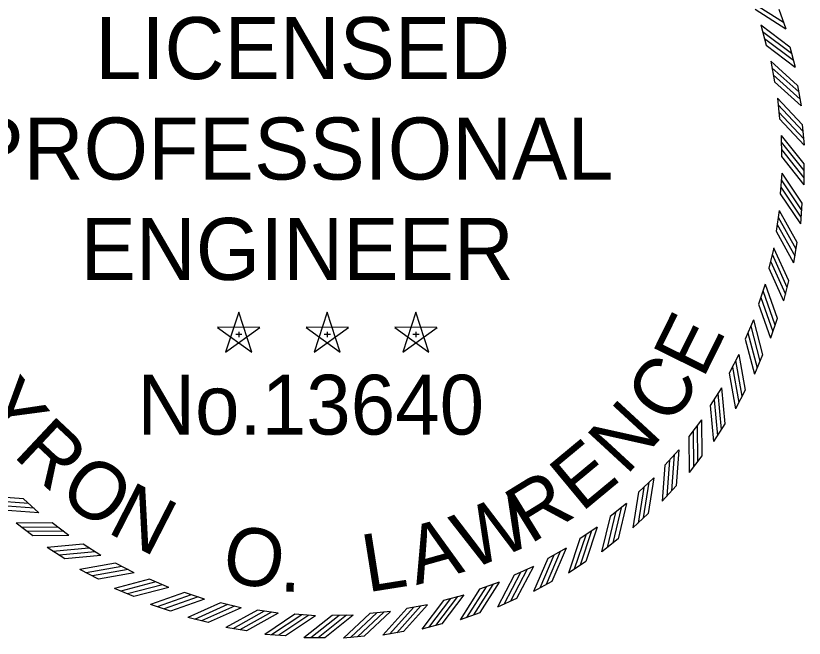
# Model space of a CAD drawing. Extents: x 166 to 3995, y -61 to 2074.
# Drawn here: x 2721.4 to 2926.8, y 412.6 to 574.8 of the extents above; entities that cross this region are included whole.
import ezdxf

# ---------------------------------------------------------------- set-up
doc = ezdxf.new("R2010")
doc.units = 0
doc.layers.add('STAMP_Byron', color=7, linetype='Continuous')

msp = doc.modelspace()

# ---------------------------------------------------------------- linework, layer by layer
at = {"layer": 'STAMP_Byron'}
for p, q in [((2920.12, 576.55), (2921.94, 571.42)), ((2920.12, 576.55), (2921.94, 571.42)), ((2915.51, 572.41), (2916.9, 567.14)), ((2915.51, 572.41), (2916.9, 567.14)), ((2923, 566.71), (2924.38, 561.44)), ((2923, 566.71), (2924.38, 561.44)), ((2918.06, 562.96), (2919.01, 557.59)), ((2918.06, 562.96), (2919.01, 557.59)), ((2925.05, 556.66), (2926, 551.3)), ((2925.05, 556.66), (2926, 551.3)), ((2919.82, 553.34), (2920.32, 547.91)), ((2919.82, 553.34), (2920.32, 547.91)), ((2926.27, 546.47), (2926.77, 541.06)), ((2926.27, 546.47), (2926.77, 541.06)), ((2920.78, 543.6), (2920.83, 538.14)), ((2920.78, 543.6), (2920.83, 538.14)), ((2926.64, 536.22), (2926.69, 530.78)), ((2926.64, 536.22), (2926.69, 530.78)), ((2920.93, 533.81), (2920.53, 528.37)), ((2920.93, 533.81), (2920.53, 528.37)), ((2926.16, 525.98), (2925.76, 520.55)), ((2926.16, 525.98), (2925.76, 520.55)), ((2920.28, 524.04), (2919.43, 518.66)), ((2920.28, 524.04), (2919.43, 518.66)), ((2924.84, 515.81), (2924, 510.43)), ((2924.84, 515.81), (2924, 510.43)), ((2918.82, 514.37), (2917.53, 509.07)), ((2918.82, 514.37), (2917.53, 509.07)), ((2922.69, 505.78), (2921.4, 500.5)), ((2922.69, 505.78), (2921.4, 500.5)), ((2916.56, 504.84), (2914.84, 499.67)), ((2916.56, 504.84), (2914.84, 499.67)), ((2779.46, 497.61), (2776.06, 487.16)), ((2779.46, 497.61), (2776.06, 487.16)), ((2782.86, 487.17), (2779.47, 497.62)), ((2782.86, 487.17), (2779.47, 497.62)), ((2802.54, 497.61), (2799.14, 487.16)), ((2802.54, 497.61), (2799.14, 487.16)), ((2805.93, 487.17), (2802.55, 497.62)), ((2805.93, 487.17), (2802.55, 497.62)), ((2825.62, 497.61), (2822.22, 487.16)), ((2825.62, 497.61), (2822.22, 487.16)), ((2829.01, 487.17), (2825.63, 497.62)), ((2829.01, 487.17), (2825.63, 497.62)), ((2913.53, 495.54), (2911.39, 490.52)), ((2913.53, 495.54), (2911.39, 490.52)), ((2919.71, 495.97), (2917.99, 490.81)), ((2919.71, 495.97), (2917.99, 490.81)), ((2784.95, 493.62), (2773.97, 493.63)), ((2784.95, 493.62), (2773.97, 493.63)), ((2773.98, 493.62), (2782.86, 487.15)), ((2773.98, 493.62), (2782.86, 487.15)), ((2776.07, 487.17), (2784.96, 493.62)), ((2776.07, 487.17), (2784.96, 493.62)), ((2808.03, 493.62), (2797.05, 493.63)), ((2808.03, 493.62), (2797.05, 493.63)), ((2797.05, 493.62), (2805.93, 487.15)), ((2797.05, 493.62), (2805.93, 487.15)), ((2799.15, 487.17), (2808.04, 493.62)), ((2799.15, 487.17), (2808.04, 493.62)), ((2831.11, 493.62), (2820.12, 493.63)), ((2831.11, 493.62), (2820.12, 493.63)), ((2820.13, 493.62), (2829.01, 487.15)), ((2820.13, 493.62), (2829.01, 487.15)), ((2822.23, 487.17), (2831.12, 493.62)), ((2822.23, 487.17), (2831.12, 493.62)), ((2778.68, 491.86), (2780.31, 491.86)), ((2778.68, 491.86), (2780.31, 491.86)), ((2779.47, 492.45), (2779.47, 491.07)), ((2779.47, 492.45), (2779.47, 491.07)), ((2801.76, 491.86), (2803.39, 491.86)), ((2801.76, 491.86), (2803.39, 491.86)), ((2802.55, 492.45), (2802.55, 491.07)), ((2802.55, 492.45), (2802.55, 491.07)), ((2824.84, 491.86), (2826.47, 491.86)), ((2824.84, 491.86), (2826.47, 491.86)), ((2825.63, 492.45), (2825.63, 491.07)), ((2825.63, 492.45), (2825.63, 491.07)), ((2909.74, 486.51), (2907.19, 481.69)), ((2909.74, 486.51), (2907.19, 481.69)), ((2915.93, 486.43), (2913.79, 481.43)), ((2915.93, 486.43), (2913.79, 481.43)), ((2905.22, 477.83), (2902.27, 473.24)), ((2905.22, 477.83), (2902.27, 473.24)), ((2911.38, 477.24), (2908.84, 472.43)), ((2911.38, 477.24), (2908.84, 472.43)), ((2899.99, 469.56), (2896.68, 465.22)), ((2899.99, 469.56), (2896.68, 465.22)), ((2906.09, 468.46), (2903.15, 463.88)), ((2906.09, 468.46), (2903.15, 463.88)), ((2894.1, 461.74), (2890.44, 457.69)), ((2894.1, 461.74), (2890.44, 457.69)), ((2900.09, 460.14), (2896.78, 455.82)), ((2900.09, 460.14), (2896.78, 455.82)), ((2887.58, 454.44), (2883.61, 450.71)), ((2887.58, 454.44), (2883.61, 450.71)), ((2893.42, 452.35), (2889.77, 448.31)), ((2893.42, 452.35), (2889.77, 448.31)), ((2727.43, 445.31), (2723.39, 448.97)), ((2727.43, 445.31), (2723.39, 448.97)), ((2880.49, 447.7), (2876.22, 444.31)), ((2880.49, 447.7), (2876.22, 444.31)), ((2886.13, 445.13), (2882.16, 441.41)), ((2886.13, 445.13), (2882.16, 441.41)), ((2725.84, 439.32), (2721.51, 442.63)), ((2725.84, 439.32), (2721.51, 442.63)), ((2735.25, 439.42), (2730.92, 442.73)), ((2735.25, 439.42), (2730.92, 442.73)), ((2872.86, 441.56), (2868.32, 438.54)), ((2872.86, 441.56), (2868.32, 438.54)), ((2878.27, 438.55), (2874.01, 435.17)), ((2878.27, 438.55), (2874.01, 435.17)), ((2734.15, 433.32), (2729.57, 436.26)), ((2734.15, 433.32), (2729.57, 436.26)), ((2743.53, 434.19), (2738.94, 437.13)), ((2743.53, 434.19), (2738.94, 437.13)), ((2864.75, 436.08), (2859.98, 433.44)), ((2864.75, 436.08), (2859.98, 433.44)), ((2752.21, 429.67), (2747.39, 432.22)), ((2752.21, 429.67), (2747.39, 432.22)), ((2856.22, 431.29), (2851.24, 429.06)), ((2856.22, 431.29), (2851.24, 429.06)), ((2869.89, 432.63), (2865.36, 429.61)), ((2869.89, 432.63), (2865.36, 429.61)), ((2742.94, 428.03), (2738.13, 430.57)), ((2742.94, 428.03), (2738.13, 430.57)), ((2761.23, 425.88), (2756.22, 428.02)), ((2761.23, 425.88), (2756.22, 428.02)), ((2847.31, 427.22), (2842.17, 425.4)), ((2847.31, 427.22), (2842.17, 425.4)), ((2861.05, 427.42), (2856.29, 424.79)), ((2861.05, 427.42), (2856.29, 424.79)), ((2752.13, 423.48), (2747.12, 425.62)), ((2752.13, 423.48), (2747.12, 425.62)), ((2770.54, 422.85), (2765.36, 424.57)), ((2770.54, 422.85), (2765.36, 424.57)), ((2838.11, 423.9), (2832.83, 422.51)), ((2838.11, 423.9), (2832.83, 422.51)), ((2761.66, 419.7), (2756.5, 421.42)), ((2761.66, 419.7), (2756.5, 421.42)), ((2780.06, 420.59), (2774.76, 421.88)), ((2780.06, 420.59), (2774.76, 421.88)), ((2828.66, 421.35), (2823.29, 420.4)), ((2828.66, 421.35), (2823.29, 420.4)), ((2851.82, 422.97), (2846.86, 420.74)), ((2851.82, 422.97), (2846.86, 420.74)), ((2789.74, 419.13), (2784.35, 419.98)), ((2789.74, 419.13), (2784.35, 419.98)), ((2819.03, 419.59), (2813.6, 419.09)), ((2819.03, 419.59), (2813.6, 419.09)), ((2842.24, 419.29), (2837.12, 417.47)), ((2842.24, 419.29), (2837.12, 417.47)), ((2771.48, 416.72), (2766.19, 418.01)), ((2771.48, 416.72), (2766.19, 418.01)), ((2799.5, 418.48), (2794.07, 418.88)), ((2799.5, 418.48), (2794.07, 418.88)), ((2809.29, 418.63), (2803.84, 418.58)), ((2809.29, 418.63), (2803.84, 418.58)), ((2781.5, 414.57), (2776.13, 415.41)), ((2781.5, 414.57), (2776.13, 415.41)), ((2832.4, 416.41), (2827.14, 415.03)), ((2832.4, 416.41), (2827.14, 415.03)), ((2791.67, 413.25), (2786.25, 413.65)), ((2791.67, 413.25), (2786.25, 413.65)), ((2812.17, 413.14), (2806.75, 412.64)), ((2812.17, 413.14), (2806.75, 412.64)), ((2822.35, 414.36), (2816.99, 413.41)), ((2822.35, 414.36), (2816.99, 413.41)), ((2801.92, 412.77), (2796.48, 412.72)), ((2801.92, 412.77), (2796.48, 412.72))]:
    msp.add_line(p, q, dxfattribs=at)
for points in [[(2913.42, 578.2), (2921.35, 573.13)], [(2913.42, 578.2), (2921.35, 573.13)], [(2914.01, 576.49), (2921.94, 571.42)], [(2914.01, 576.49), (2921.94, 571.42)], [(2915.5, 572.42), (2922.99, 566.71)], [(2915.5, 572.42), (2922.99, 566.71)], [(2915.93, 570.72), (2923.42, 565.01)], [(2915.93, 570.72), (2923.42, 565.01)], [(2916.45, 568.9), (2923.94, 563.2)], [(2916.45, 568.9), (2923.94, 563.2)], [(2916.9, 567.15), (2924.39, 561.44)], [(2916.9, 567.15), (2924.39, 561.44)], [(2918.05, 562.97), (2925.05, 556.66)], [(2918.05, 562.97), (2925.05, 556.66)], [(2918.34, 561.24), (2925.33, 554.94)], [(2918.34, 561.24), (2925.33, 554.94)], [(2918.71, 559.39), (2925.7, 553.08)], [(2918.71, 559.39), (2925.7, 553.08)], [(2919.01, 557.6), (2926, 551.29)], [(2919.01, 557.6), (2926, 551.29)], [(2919.82, 553.34), (2926.26, 546.48)], [(2919.82, 553.34), (2926.26, 546.48)], [(2919.96, 551.6), (2926.41, 544.74)], [(2919.96, 551.6), (2926.41, 544.74)], [(2920.18, 549.72), (2926.62, 542.86)], [(2920.18, 549.72), (2926.62, 542.86)], [(2920.33, 547.91), (2926.77, 541.05)], [(2920.33, 547.91), (2926.77, 541.05)], [(2920.78, 543.6), (2926.63, 536.23)], [(2920.78, 543.6), (2926.63, 536.23)], [(2920.78, 541.85), (2926.63, 534.48)], [(2920.78, 541.85), (2926.63, 534.48)], [(2920.84, 539.96), (2926.69, 532.59)], [(2920.84, 539.96), (2926.69, 532.59)], [(2920.84, 538.15), (2926.69, 530.78)], [(2920.84, 538.15), (2926.69, 530.78)], [(2920.79, 532.07), (2926.01, 524.24)], [(2920.79, 532.07), (2926.01, 524.24)], [(2920.93, 533.82), (2926.16, 525.99)], [(2920.93, 533.82), (2926.16, 525.99)], [(2920.69, 530.18), (2925.92, 522.35)], [(2920.69, 530.18), (2925.92, 522.35)], [(2920.54, 528.38), (2925.77, 520.55)], [(2920.54, 528.38), (2925.77, 520.55)], [(2920.27, 524.05), (2924.84, 515.82)], [(2920.27, 524.05), (2924.84, 515.82)], [(2919.99, 522.32), (2924.55, 514.09)], [(2919.99, 522.32), (2924.55, 514.09)], [(2919.73, 520.45), (2924.3, 512.22)], [(2919.73, 520.45), (2924.3, 512.22)], [(2919.44, 518.66), (2924, 510.43)], [(2919.44, 518.66), (2924, 510.43)], [(2918.81, 514.37), (2922.68, 505.79)], [(2918.81, 514.37), (2922.68, 505.79)], [(2918.38, 512.68), (2922.25, 504.09)], [(2918.38, 512.68), (2922.25, 504.09)], [(2917.98, 510.83), (2921.85, 502.25)], [(2917.98, 510.83), (2921.85, 502.25)], [(2917.53, 509.07), (2921.4, 500.49)], [(2917.53, 509.07), (2921.4, 500.49)], [(2915.99, 503.19), (2919.14, 494.32)], [(2915.99, 503.19), (2919.14, 494.32)], [(2916.56, 504.85), (2919.71, 495.98)], [(2916.56, 504.85), (2919.71, 495.98)], [(2915.43, 501.39), (2918.58, 492.51)], [(2915.43, 501.39), (2918.58, 492.51)], [(2914.85, 499.67), (2917.99, 490.8)], [(2914.85, 499.67), (2917.99, 490.8)], [(2913.53, 495.54), (2915.93, 486.44)], [(2913.53, 495.54), (2915.93, 486.44)], [(2912.82, 493.94), (2915.23, 484.84)], [(2912.82, 493.94), (2915.23, 484.84)], [(2912.12, 492.19), (2914.52, 483.08)], [(2912.12, 492.19), (2914.52, 483.08)], [(2911.39, 490.53), (2913.8, 481.42)], [(2911.39, 490.53), (2913.8, 481.42)], [(2908.9, 484.98), (2910.55, 475.71)], [(2908.9, 484.98), (2910.55, 475.71)], [(2909.74, 486.52), (2911.38, 477.25)], [(2909.74, 486.52), (2911.38, 477.25)], [(2908.06, 483.29), (2909.7, 474.02)], [(2908.06, 483.29), (2909.7, 474.02)], [(2907.19, 481.7), (2908.84, 472.43)], [(2907.19, 481.7), (2908.84, 472.43)], [(2905.21, 477.84), (2906.09, 468.47)], [(2905.21, 477.84), (2906.09, 468.47)], [(2903.27, 474.76), (2904.15, 465.39)], [(2903.27, 474.76), (2904.15, 465.39)], [(2904.26, 476.37), (2905.13, 467)], [(2904.26, 476.37), (2905.13, 467)], [(2902.28, 473.24), (2903.15, 463.87)], [(2902.28, 473.24), (2903.15, 463.87)], [(2899.99, 469.56), (2900.09, 460.15)], [(2899.99, 469.56), (2900.09, 460.15)], [(2897.8, 466.66), (2897.9, 457.24)], [(2897.8, 466.66), (2897.9, 457.24)], [(2898.91, 468.18), (2899.01, 458.77)], [(2898.91, 468.18), (2899.01, 458.77)], [(2896.69, 465.22), (2896.78, 455.81)], [(2896.69, 465.22), (2896.78, 455.81)], [(2892.91, 460.46), (2892.23, 451.07)], [(2892.91, 460.46), (2892.23, 451.07)], [(2894.1, 461.75), (2893.42, 452.36)], [(2894.1, 461.75), (2893.42, 452.36)], [(2891.68, 459.03), (2891, 449.64)], [(2891.68, 459.03), (2891, 449.64)], [(2890.45, 457.7), (2889.77, 448.31)], [(2890.45, 457.7), (2889.77, 448.31)], [(2887.59, 454.44), (2886.13, 445.14)], [(2887.59, 454.44), (2886.13, 445.14)], [(2884.95, 451.94), (2883.49, 442.63)], [(2884.95, 451.94), (2883.49, 442.63)], [(2886.3, 453.26), (2884.84, 443.96)], [(2886.3, 453.26), (2884.84, 443.96)], [(2883.61, 450.71), (2882.16, 441.41)], [(2883.61, 450.71), (2882.16, 441.41)], [(2723.39, 448.96), (2714, 449.64)], [(2723.39, 448.96), (2714, 449.64)], [(2724.72, 447.73), (2715.34, 448.41)], [(2724.72, 447.73), (2715.34, 448.41)], [(2726.15, 446.5), (2716.77, 447.18)], [(2726.15, 446.5), (2716.77, 447.18)], [(2727.44, 445.31), (2718.05, 445.99)], [(2727.44, 445.31), (2718.05, 445.99)], [(2879.11, 446.63), (2876.89, 437.48)], [(2879.11, 446.63), (2876.89, 437.48)], [(2880.49, 447.7), (2878.27, 438.55)], [(2880.49, 447.7), (2878.27, 438.55)], [(2876.22, 444.31), (2874, 435.16)], [(2876.22, 444.31), (2874, 435.16)], [(2877.65, 445.42), (2875.43, 436.27)], [(2877.65, 445.42), (2875.43, 436.27)], [(2730.92, 442.72), (2721.51, 442.63)], [(2730.92, 442.72), (2721.51, 442.63)], [(2732.35, 441.61), (2722.94, 441.51)], [(2732.35, 441.61), (2722.94, 441.51)], [(2872.86, 441.57), (2869.9, 432.64)], [(2872.86, 441.57), (2869.9, 432.64)], [(2733.88, 440.49), (2724.46, 440.4)], [(2733.88, 440.49), (2724.46, 440.4)], [(2869.85, 439.53), (2866.88, 430.6)], [(2869.85, 439.53), (2866.88, 430.6)], [(2871.4, 440.61), (2868.43, 431.68)], [(2871.4, 440.61), (2868.43, 431.68)], [(2735.26, 439.42), (2725.85, 439.32)], [(2735.26, 439.42), (2725.85, 439.32)], [(2868.33, 438.54), (2865.36, 429.61)], [(2868.33, 438.54), (2865.36, 429.61)], [(2738.94, 437.13), (2729.56, 436.26)], [(2738.94, 437.13), (2729.56, 436.26)], [(2740.46, 436.14), (2731.08, 435.26)], [(2740.46, 436.14), (2731.08, 435.26)], [(2864.75, 436.09), (2861.06, 427.43)], [(2864.75, 436.09), (2861.06, 427.43)], [(2742.07, 435.15), (2732.7, 434.28)], [(2742.07, 435.15), (2732.7, 434.28)], [(2743.54, 434.2), (2734.16, 433.32)], [(2743.54, 434.2), (2734.16, 433.32)], [(2859.98, 433.44), (2856.29, 424.79)], [(2859.98, 433.44), (2856.29, 424.79)], [(2861.58, 434.31), (2857.89, 425.65)], [(2861.58, 434.31), (2857.89, 425.65)], [(2863.21, 435.26), (2859.52, 426.6)], [(2863.21, 435.26), (2859.52, 426.6)], [(2747.39, 432.22), (2738.12, 430.57)], [(2747.39, 432.22), (2738.12, 430.57)], [(2748.99, 431.35), (2739.72, 429.71)], [(2748.99, 431.35), (2739.72, 429.71)], [(2856.22, 431.3), (2851.82, 422.98)], [(2856.22, 431.3), (2851.82, 422.98)], [(2750.68, 430.51), (2741.41, 428.86)], [(2750.68, 430.51), (2741.41, 428.86)], [(2752.22, 429.67), (2742.95, 428.03)], [(2752.22, 429.67), (2742.95, 428.03)], [(2852.91, 429.78), (2848.51, 421.46)], [(2852.91, 429.78), (2848.51, 421.46)], [(2854.62, 430.6), (2850.22, 422.27)], [(2854.62, 430.6), (2850.22, 422.27)], [(2756.22, 428.02), (2747.12, 425.61)], [(2756.22, 428.02), (2747.12, 425.61)], [(2757.88, 427.29), (2748.78, 424.89)], [(2757.88, 427.29), (2748.78, 424.89)], [(2847.32, 427.23), (2842.25, 419.3)], [(2847.32, 427.23), (2842.25, 419.3)], [(2851.25, 429.06), (2846.85, 420.73)], [(2851.25, 429.06), (2846.85, 420.73)], [(2759.63, 426.58), (2750.53, 424.18)], [(2759.63, 426.58), (2750.53, 424.18)], [(2761.24, 425.88), (2752.14, 423.48)], [(2761.24, 425.88), (2752.14, 423.48)], [(2842.18, 425.4), (2837.11, 417.47)], [(2842.18, 425.4), (2837.11, 417.47)], [(2843.89, 425.99), (2838.83, 418.06)], [(2843.89, 425.99), (2838.83, 418.06)], [(2845.66, 426.66), (2840.59, 418.73)], [(2845.66, 426.66), (2840.59, 418.73)], [(2765.37, 424.56), (2756.49, 421.42)], [(2765.37, 424.56), (2756.49, 421.42)], [(2767.08, 423.97), (2758.21, 420.83)], [(2767.08, 423.97), (2758.21, 420.83)], [(2768.89, 423.42), (2760.02, 420.27)], [(2768.89, 423.42), (2760.02, 420.27)], [(2836.42, 423.48), (2830.71, 415.99)], [(2836.42, 423.48), (2830.71, 415.99)], [(2838.11, 423.91), (2832.41, 416.42)], [(2838.11, 423.91), (2832.41, 416.42)], [(2770.54, 422.85), (2761.67, 419.7)], [(2770.54, 422.85), (2761.67, 419.7)], [(2774.77, 421.88), (2766.18, 418.01)], [(2774.77, 421.88), (2766.18, 418.01)], [(2776.52, 421.43), (2767.94, 417.56)], [(2776.52, 421.43), (2767.94, 417.56)], [(2778.37, 421.02), (2769.79, 417.16)], [(2778.37, 421.02), (2769.79, 417.16)], [(2826.94, 421.07), (2820.63, 414.08)], [(2826.94, 421.07), (2820.63, 414.08)], [(2828.66, 421.36), (2822.36, 414.36)], [(2828.66, 421.36), (2822.36, 414.36)], [(2832.84, 422.51), (2827.13, 415.02)], [(2832.84, 422.51), (2827.13, 415.02)], [(2834.6, 422.96), (2828.89, 415.47)], [(2834.6, 422.96), (2828.89, 415.47)], [(2780.07, 420.59), (2771.49, 416.73)], [(2780.07, 420.59), (2771.49, 416.73)], [(2784.36, 419.97), (2776.12, 415.41)], [(2784.36, 419.97), (2776.12, 415.41)], [(2786.14, 419.68), (2777.91, 415.11)], [(2786.14, 419.68), (2777.91, 415.11)], [(2788.02, 419.42), (2779.78, 414.86)], [(2788.02, 419.42), (2779.78, 414.86)], [(2789.75, 419.14), (2781.51, 414.57)], [(2789.75, 419.14), (2781.51, 414.57)], [(2813.61, 419.08), (2806.75, 412.64)], [(2813.61, 419.08), (2806.75, 412.64)], [(2815.41, 419.23), (2808.55, 412.79)], [(2815.41, 419.23), (2808.55, 412.79)], [(2817.29, 419.45), (2810.43, 413)], [(2817.29, 419.45), (2810.43, 413)], [(2819.04, 419.59), (2812.18, 413.15)], [(2819.04, 419.59), (2812.18, 413.15)], [(2823.29, 420.4), (2816.99, 413.41)], [(2823.29, 420.4), (2816.99, 413.41)], [(2825.08, 420.7), (2818.78, 413.71)], [(2825.08, 420.7), (2818.78, 413.71)], [(2794.07, 418.87), (2786.24, 413.64)], [(2794.07, 418.87), (2786.24, 413.64)], [(2795.88, 418.72), (2788.05, 413.49)], [(2795.88, 418.72), (2788.05, 413.49)], [(2797.77, 418.62), (2789.94, 413.4)], [(2797.77, 418.62), (2789.94, 413.4)], [(2799.51, 418.48), (2791.68, 413.25)], [(2799.51, 418.48), (2791.68, 413.25)], [(2803.84, 418.57), (2796.47, 412.72)], [(2803.84, 418.57), (2796.47, 412.72)], [(2805.66, 418.57), (2798.29, 412.72)], [(2805.66, 418.57), (2798.29, 412.72)], [(2807.55, 418.63), (2800.18, 412.78)], [(2807.55, 418.63), (2800.18, 412.78)], [(2809.3, 418.63), (2801.93, 412.78)], [(2809.3, 418.63), (2801.93, 412.78)]]:
    msp.add_lwpolyline(points, dxfattribs=at)

# ---------------------------------------------------------------- texts
for s, height, p in [('LICENSED', 16.155, (2742.13, 558.29)), ('LICENSED', 16.155, (2742.13, 558.29)), ('PROFESSIONAL', 16.1547, (2709.05, 532.13)), ('PROFESSIONAL', 16.1547, (2709.05, 532.13)), ('ENGINEER', 16.155, (2738.28, 505.97)), ('ENGINEER', 16.155, (2738.28, 505.97)), ('No.13640', 15.578, (2753.05, 465.69)), ('No.13640', 15.578, (2753.05, 465.69))]:
    msp.add_text(s, height=height, dxfattribs=at).set_placement(p)
for s, rotation, p in [('E', 63.7362, (2900.42, 480.03)), ('E', 63.7362, (2900.42, 480.03)), ('C', 56.0754, (2891.98, 467.56)), ('C', 56.0754, (2891.98, 467.56)), ('Y', 308.8241, (2710.55, 472.49)), ('Y', 308.8241, (2710.55, 472.49)), ('N', 47.3202, (2880.4, 454.83)), ('N', 47.3202, (2880.4, 454.83)), ('R', 316.8497, (2720.44, 460.2)), ('R', 316.8497, (2720.44, 460.2)), ('E', 39.6594, (2868.78, 445.26)), ('E', 39.6594, (2868.78, 445.26)), ('O', 324.8753, (2731.95, 449.41)), ('O', 324.8753, (2731.95, 449.41)), ('R', 31.6338, (2855.35, 436.98)), ('R', 31.6338, (2855.35, 436.98)), ('N', 332.9009, (2744.85, 440.34)), ('N', 332.9009, (2744.85, 440.34)), ('W', 22.8786, (2839.54, 430.19)), ('W', 22.8786, (2839.54, 430.19)), ('O', 349.3169, (2774.5, 427.82)), ('O', 349.3169, (2774.5, 427.82)), ('A', 15.5826, (2825.7, 426.43)), ('A', 15.5826, (2825.7, 426.43)), ('L', 9.0162, (2812.92, 424.56)), ('L', 9.0162, (2812.92, 424.56)), ('.', 357.3425, (2790, 424.89)), ('.', 357.3425, (2790, 424.89))]:
    msp.add_text(s, height=15.03, rotation=rotation, dxfattribs=at).set_placement(p)

doc.saveas('drawing.dxf')
